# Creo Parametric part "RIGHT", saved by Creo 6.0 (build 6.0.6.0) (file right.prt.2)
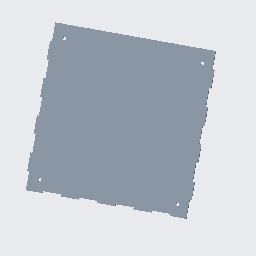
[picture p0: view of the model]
Units: Inch lbm Second (Pro/E Default); INCH, POUND, SECS

Created from: INLBS_PART_SOLID.PRT

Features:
  1. datum plane "RIGHT"
  2. datum plane "TOP"
  3. datum plane "FRONT"
  4. coordinate system
  5. sketch "Sketch 1"
  6. extrusion "Extrude 1"
  7. sketch "Sketch 2"
  8. extruded cut "Extrude 2"

Surfaces: 54 plane, 4 cylinder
